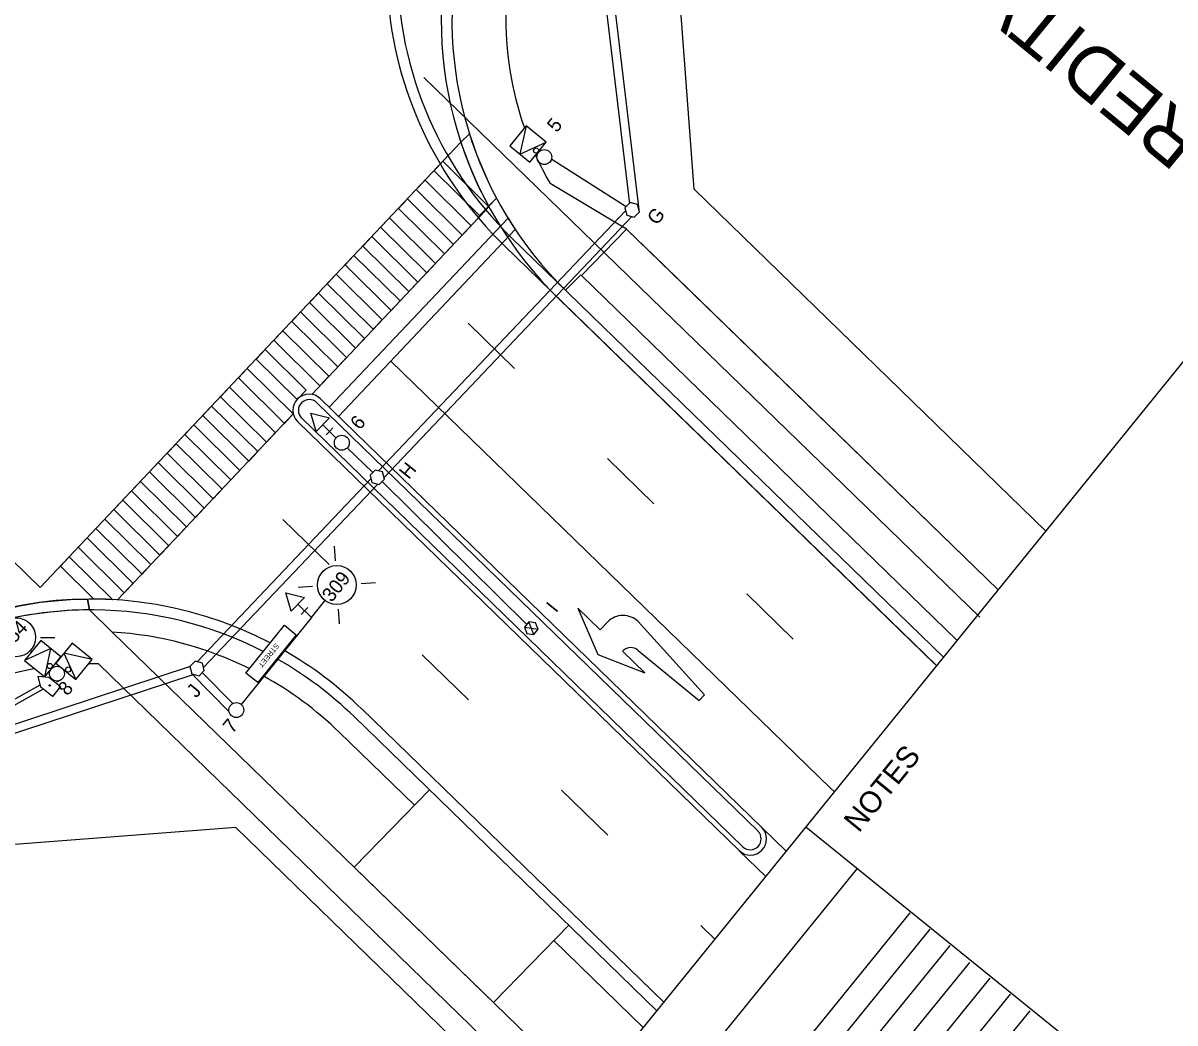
# Model space of a CAD drawing. Extents: x 592613 to 600223, y 4837996 to 4840103.
# Drawn here: x 593021.3 to 593074.7, y 4839279.7 to 4839326.1 of the extents above; entities that cross this region are included whole.
import ezdxf

# ---------------------------------------------------------------- set-up
doc = ezdxf.new("R2010")
doc.units = 0
for name, color, linetype in [('ENG_BORDER', 7, 'Continuous'), ('ENG_BUS-PAD', 7, 'Continuous'), ('ENG_CURB-BACK', 7, 'Continuous'), ('ENG_CURBSTOP', 7, 'Continuous'), ('ENG_EPAVT', 7, 'Continuous'), ('ENG_KILLSTRIP', 7, 'Continuous'), ('ENG_MULTI-TRAIL', 7, 'Continuous'), ('ENG_SH_MULTI-TRAIL', 7, 'Continuous'), ('ENG_SIDEWALK', 7, 'Continuous'), ('ENG_TITLEBLOCK', 7, 'Continuous'), ('ENG_TX_TITLEBLOCK', 7, 'Continuous'), ('Level 1', 7, 'Continuous'), ('Level 12', 7, 'Continuous'), ('Level 31', 7, 'Continuous'), ('Level 32', 7, 'Continuous'), ('Level 9', 7, 'Continuous'), ('PMK_LANE', 7, 'Continuous'), ('PMK_LANE_3-6', 7, 'Continuous'), ('ROW_ENG_ROW', 7, 'Continuous'), ('TCS_100mm-NEW', 7, 'Continuous'), ('TCS_50mm-NEW', 7, 'Continuous'), ('TCS_75mm-NEW', 7, 'Continuous'), ('TCS_ELEC-CHAMBER-NEW', 7, 'Continuous'), ('TCS_LUMINAIRE-NEW', 7, 'Continuous'), ('TCS_POLE-NEW', 7, 'Continuous'), ('TCS_PUSHBUTTON', 7, 'Continuous'), ('TCS_RADAR', 7, 'Continuous'), ('TCS_SIGN', 7, 'Continuous'), ('TCS_SIGNALHEAD', 7, 'Continuous')]:
    doc.layers.add(name, color=color, linetype=linetype)

msp = doc.modelspace()

# ---------------------------------------------------------------- linework, layer by layer
at = {"layer": 'ENG_BORDER'}
for p, q in [((593077.324, 4839272.823), (593057.566, 4839288.798)), ((593017.004, 4839234.009), (593059.952, 4839286.868))]:
    msp.add_line(p, q, dxfattribs=at)
at = {"layer": 'ENG_BUS-PAD'}
for p, q in [((593040.134, 4839290.531), (593036.65, 4839286.945)), ((593043.105, 4839280.674), (593036.65, 4839286.945)), ((593046.589, 4839284.26), (593043.105, 4839280.674))]:
    msp.add_line(p, q, dxfattribs=at)
at = {"layer": 'ENG_CURB-BACK'}
for p, q in [((593063.95, 4839296.672), (593043.953, 4839316.099)), ((593055.355, 4839288.609), (593034.912, 4839308.469)), ((593054.658, 4839287.891), (593034.204, 4839307.762)), ((593050.671, 4839280.294), (593036.643, 4839293.922))]:
    msp.add_line(p, q, dxfattribs=at)
for centre, radius, start, end in [((593058.676, 4839326.195), 17.5, 167.7306, 225.8289), ((593056.147, 4839328.651), 17.5, 178.3407, 225.8289), ((593034.558, 4839308.115), 0.5, 45.2459, 225.2459), ((593024.449, 4839281.37), 17.5, 62.8455, 116.2063), ((593024.449, 4839281.37), 17.5, 45.8289, 60.4988), ((593055.001, 4839288.255), 0.5, 226.4119, 45.2459)]:
    msp.add_arc(centre, radius, start, end, dxfattribs=at)
at = {"layer": 'ENG_CURBSTOP'}
for p, q in [((593041.985, 4839320.934), (593041.589, 4839320.535)), ((593043.243, 4839317.942), (593042.373, 4839317.064)), ((593024.375, 4839298.87), (593024.286, 4839299.369))]:
    msp.add_line(p, q, dxfattribs=at)
for points in [[(593043.243, 4839317.942), (593042.876, 4839317.571), (593042.412, 4839318.481), (593042.09, 4839319.2), (593041.59, 4839320.538), (593041.985, 4839320.934), (593042.33, 4839319.943), (593042.836, 4839318.755), (593043.006, 4839318.376)], [(593024.375, 4839298.87), (593023.359, 4839298.836), (593022.22, 4839298.728), (593021.245, 4839298.574), (593019.537, 4839298.161), (593019.155, 4839298.567), (593021.133, 4839299.062), (593021.663, 4839299.153), (593022.119, 4839299.219), (593022.783, 4839299.293), (593023.495, 4839299.345), (593024.042, 4839299.366), (593024.286, 4839299.369)]]:
    msp.add_lwpolyline(points, close=True, dxfattribs=at)
at = {"layer": 'ENG_EPAVT'}
for p, q in [((593063.634, 4839296.283), (593043.605, 4839315.74)), ((593055.529, 4839288.788), (593035.086, 4839308.648)), ((593054.484, 4839287.712), (593034.03, 4839307.583)), ((593050.988, 4839280.684), (593036.992, 4839294.281))]:
    msp.add_line(p, q, dxfattribs=at)
for centre, radius, start, end in [((593058.676, 4839326.195), 18, 166.783, 225.8289), ((593056.147, 4839328.651), 18, 184.2333, 225.8289), ((593034.558, 4839308.115), 0.75, 45.2459, 225.2459), ((593024.449, 4839281.37), 18, 62.5135, 142.6377), ((593024.449, 4839281.37), 16.5, 63.5712, 86.5779), ((593024.449, 4839281.37), 18, 45.8289, 60.2342), ((593024.449, 4839281.37), 16.5, 45.8289, 61.0962), ((593055.001, 4839288.255), 0.75, 226.4119, 45.2459)]:
    msp.add_arc(centre, radius, start, end, dxfattribs=at)
at = {"layer": 'ENG_KILLSTRIP'}
for p, q in [((593064.582, 4839297.452), (593047.178, 4839314.36)), ((593039.437, 4839289.814), (593035.946, 4839293.205)), ((593050.039, 4839279.514), (593045.892, 4839283.543))]:
    msp.add_line(p, q, dxfattribs=at)
at = {"layer": 'ENG_MULTI-TRAIL'}
for p, q in [((593049.269, 4839316.512), (593047.178, 4839314.36)), ((593066.479, 4839299.792), (593049.269, 4839316.512))]:
    msp.add_line(p, q, dxfattribs=at)
at = {"layer": 'ENG_SH_MULTI-TRAIL'}
for p, q in [((593039.879, 4839323.542), (593065.627, 4839298.528)), ((593046.133, 4839313.284), (593063.537, 4839296.376))]:
    msp.add_line(p, q, dxfattribs=at)
msp.add_lwpolyline([(593066.479, 4839299.792), (593050.537, 4839315.28), (593049.269, 4839316.512), (593047.178, 4839314.36), (593047.178, 4839314.36), (593064.582, 4839297.452)], dxfattribs=at)
at = {"layer": 'ENG_SIDEWALK'}
for p, q in [((593049.269, 4839316.512), (593045.728, 4839318.621)), ((593047.142, 4839314.395), (593046.419, 4839313.666)), ((593025.434, 4839297.841), (593024.375, 4839298.87)), ((593047.51, 4839276.395), (593025.434, 4839297.841)), ((593046.561, 4839275.225), (593024.799, 4839296.366))]:
    msp.add_line(p, q, dxfattribs=at)
for centre, start, end in [((593058.676, 4839326.195), 178.3521, 199.4407), ((593058.676, 4839326.195), 204.683, 210.3244), ((593024.449, 4839281.37), 88.6623, 90.4558), ((593024.449, 4839281.37), 100.1986, 113.33)]:
    msp.add_arc(centre, 15, start, end, dxfattribs=at)
at = {"layer": 'ENG_TITLEBLOCK'}
msp.add_line((593014.678, 4839235.899), (593087.391, 4839325.585), dxfattribs=at)
at = {"layer": 'Level 1'}
msp.add_line((593021.646, 4839296.981), (593021.705, 4839296.933), dxfattribs=at)
at = {"layer": 'Level 12'}
for p, q in [((593048.043, 4839297.948), (593047.013, 4839298.946)), ((593047.013, 4839298.946), (593047.934, 4839296.805)), ((593048.388, 4839298.304), (593048.043, 4839297.948)), ((593052.879, 4839294.931), (593049.802, 4839298.327)), ((593047.934, 4839296.805), (593050.104, 4839295.953)), ((593050.104, 4839295.953), (593049.073, 4839296.951)), ((593049.801, 4839296.983), (593052.624, 4839294.668)), ((593052.624, 4839294.668), (593052.879, 4839294.931))]:
    msp.add_line(p, q, dxfattribs=at)
for centre, radius, start, end in [((593049.107, 4839297.608), 1, 45.9051, 135.9273), ((593049.453, 4839296.624), 0.5, 45.8987, 135.9224)]:
    msp.add_arc(centre, radius, start, end, dxfattribs=at)
at = {"layer": 'Level 31'}
for p, q in [((593019.478, 4839231.999), (593062.405, 4839284.832)), ((593022.481, 4839233.799), (593063.333, 4839284.078)), ((593021.335, 4839230.491), (593064.261, 4839283.324)), ((593022.263, 4839229.736), (593065.161, 4839282.536)), ((593023.19, 4839228.983), (593066.104, 4839281.799)), ((593024.118, 4839228.229), (593067.045, 4839281.062)), ((593025.046, 4839227.475), (593067.959, 4839280.291))]:
    msp.add_line(p, q, dxfattribs=at)
at = {"layer": 'Level 9'}
msp.add_line((593023.084, 4839295.641), (593022.86, 4839295.522), dxfattribs=at)
at = {"layer": 'PMK_LANE'}
for p, q in [((593000.151, 4839321.221), (593022.099, 4839299.906)), ((593022.099, 4839299.906), (593041.589, 4839320.535)), ((593040.757, 4839319.655), (593040.345, 4839319.218)), ((593040.345, 4839319.218), (593042.478, 4839317.108)), ((593042.891, 4839317.544), (593040.757, 4839319.655)), ((593039.933, 4839318.782), (593039.521, 4839318.346)), ((593042.066, 4839316.672), (593039.933, 4839318.782)), ((593039.521, 4839318.346), (593041.654, 4839316.235)), ((593039.109, 4839317.91), (593038.697, 4839317.473)), ((593041.242, 4839315.799), (593039.109, 4839317.91)), ((593034.681, 4839308.855), (593042.891, 4839317.544)), ((593038.697, 4839317.473), (593040.83, 4839315.363)), ((593042.478, 4839317.108), (593042.891, 4839317.544)), ((593035.49, 4839308.255), (593043.773, 4839317.021)), ((593038.284, 4839317.037), (593037.872, 4839316.601)), ((593037.872, 4839316.601), (593040.005, 4839314.49)), ((593040.418, 4839314.927), (593038.284, 4839317.037)), ((593041.654, 4839316.235), (593042.066, 4839316.672)), ((593035.921, 4839307.837), (593044.106, 4839316.501)), ((593037.46, 4839316.165), (593037.048, 4839315.728)), ((593039.593, 4839314.054), (593037.46, 4839316.165)), ((593037.048, 4839315.728), (593039.181, 4839313.618)), ((593040.83, 4839315.363), (593041.242, 4839315.799)), ((593036.636, 4839315.292), (593036.224, 4839314.856)), ((593038.769, 4839313.182), (593036.636, 4839315.292)), ((593040.005, 4839314.49), (593040.418, 4839314.927)), ((593035.811, 4839314.42), (593035.399, 4839313.983)), ((593037.945, 4839312.309), (593035.811, 4839314.42)), ((593036.224, 4839314.856), (593038.357, 4839312.745)), ((593035.399, 4839313.983), (593037.532, 4839311.873)), ((593039.181, 4839313.618), (593039.593, 4839314.054)), ((593034.987, 4839313.547), (593034.575, 4839313.111)), ((593037.12, 4839311.437), (593034.987, 4839313.547)), ((593034.575, 4839313.111), (593036.708, 4839311)), ((593038.357, 4839312.745), (593038.769, 4839313.182)), ((593034.163, 4839312.675), (593033.751, 4839312.238)), ((593033.751, 4839312.238), (593035.884, 4839310.128)), ((593036.296, 4839310.564), (593034.163, 4839312.675)), ((593037.532, 4839311.873), (593037.945, 4839312.309)), ((593033.338, 4839311.802), (593032.926, 4839311.366)), ((593035.472, 4839309.692), (593033.338, 4839311.802)), ((593032.926, 4839311.366), (593035.059, 4839309.255)), ((593036.708, 4839311), (593037.12, 4839311.437)), ((593032.514, 4839310.93), (593032.102, 4839310.493)), ((593034.413, 4839309.051), (593032.514, 4839310.93)), ((593032.102, 4839310.493), (593034.001, 4839308.614)), ((593035.884, 4839310.128), (593036.296, 4839310.564)), ((593045.801, 4839303.151), (593038.34, 4839310.398)), ((593031.69, 4839310.057), (593031.278, 4839309.621)), ((593031.278, 4839309.621), (593033.411, 4839307.51)), ((593033.823, 4839307.947), (593031.69, 4839310.057)), ((593035.059, 4839309.255), (593035.472, 4839309.692)), ((593030.865, 4839309.185), (593030.453, 4839308.748)), ((593032.999, 4839307.074), (593030.865, 4839309.185)), ((593034.001, 4839308.614), (593034.413, 4839309.051)), ((593030.453, 4839308.748), (593032.587, 4839306.638)), ((593030.041, 4839308.312), (593029.629, 4839307.876)), ((593032.174, 4839306.202), (593030.041, 4839308.312)), ((593025.68, 4839299.328), (593033.826, 4839307.95)), ((593029.217, 4839307.44), (593028.805, 4839307.003)), ((593031.35, 4839305.329), (593029.217, 4839307.44)), ((593029.629, 4839307.876), (593031.762, 4839305.765)), ((593033.411, 4839307.51), (593033.823, 4839307.947)), ((593028.805, 4839307.003), (593030.938, 4839304.893)), ((593032.587, 4839306.638), (593032.999, 4839307.074)), ((593028.392, 4839306.567), (593027.98, 4839306.131)), ((593030.526, 4839304.457), (593028.392, 4839306.567)), ((593027.98, 4839306.131), (593030.114, 4839304.02)), ((593031.762, 4839305.765), (593032.174, 4839306.202)), ((593027.568, 4839305.695), (593027.156, 4839305.258)), ((593029.701, 4839303.584), (593027.568, 4839305.695)), ((593026.744, 4839304.822), (593026.332, 4839304.386)), ((593028.877, 4839302.712), (593026.744, 4839304.822)), ((593027.156, 4839305.258), (593029.289, 4839303.148)), ((593026.332, 4839304.386), (593028.465, 4839302.275)), ((593030.114, 4839304.02), (593030.526, 4839304.457)), ((593025.92, 4839303.95), (593025.507, 4839303.513)), ((593028.053, 4839301.839), (593025.92, 4839303.95)), ((593025.507, 4839303.513), (593027.641, 4839301.403)), ((593029.289, 4839303.148), (593029.701, 4839303.584)), ((593025.095, 4839303.077), (593024.683, 4839302.641)), ((593024.683, 4839302.641), (593026.816, 4839300.53)), ((593027.228, 4839300.967), (593025.095, 4839303.077)), ((593028.465, 4839302.275), (593028.877, 4839302.712)), ((593052.257, 4839296.879), (593045.801, 4839303.151)), ((593024.271, 4839302.205), (593023.859, 4839301.768)), ((593026.404, 4839300.094), (593024.271, 4839302.205)), ((593023.859, 4839301.768), (593025.992, 4839299.658)), ((593027.641, 4839301.403), (593028.053, 4839301.839)), ((593023.447, 4839301.332), (593023.034, 4839300.896)), ((593025.458, 4839299.342), (593023.447, 4839301.332)), ((593023.034, 4839300.896), (593024.577, 4839299.37)), ((593026.816, 4839300.53), (593027.228, 4839300.967)), ((593025.992, 4839299.658), (593026.404, 4839300.094)), ((593058.713, 4839290.607), (593052.257, 4839296.879)), ((593058.891, 4839290.433), (593058.713, 4839290.607)), ((593055.553, 4839288.763), (593056.664, 4839287.686)), ((593054.488, 4839287.709), (593055.716, 4839286.517))]:
    msp.add_line(p, q, dxfattribs=at)
msp.add_lwpolyline([(593043.773, 4839317.021), (593044.106, 4839316.501), (593035.921, 4839307.837), (593035.49, 4839308.255)], close=True, dxfattribs=at)
msp.add_lwpolyline([(593030.938, 4839304.893), (593031.183, 4839305.152), (593031.35, 4839305.329)], dxfattribs=at)
msp.add_arc((593024.449, 4839281.37), 18, 86.7865, 89.5933, dxfattribs=at)
at = {"layer": 'PMK_LANE_3-6'}
for p, q in [((593044.072, 4839310.058), (593041.92, 4839312.149)), ((593050.528, 4839303.786), (593048.376, 4839305.877)), ((593033.335, 4839303.062), (593035.487, 4839300.971)), ((593056.984, 4839297.514), (593054.832, 4839299.605)), ((593039.791, 4839296.79), (593041.943, 4839294.699)), ((593046.247, 4839290.518), (593048.399, 4839288.427)), ((593052.703, 4839284.246), (593053.359, 4839283.609))]:
    msp.add_line(p, q, dxfattribs=at)
at = {"layer": 'ROW_ENG_ROW'}
for p, q in [((593052.389, 4839318.36), (593050.733, 4839340.727)), ((593068.692, 4839302.522), (593052.389, 4839318.36)), ((593031.168, 4839288.785), (593010.654, 4839287.203)), ((593045.929, 4839274.445), (593031.168, 4839288.785))]:
    msp.add_line(p, q, dxfattribs=at)
at = {"layer": 'TCS_100mm-NEW'}
for p, q in [((593049.863, 4839317.287), (593047.783, 4839334.814)), ((593038.032, 4839305.002), (593049.512, 4839317.094)), ((593036.32, 4839306.371), (593037.503, 4839305.228)), ((593029.667, 4839296.192), (593037.74, 4839304.696)), ((593017.452, 4839292.021), (593029.189, 4839295.876)), ((593029.609, 4839295.973), (593031.025, 4839294.534)), ((593022.229, 4839295.188), (593017.538, 4839292.568))]:
    msp.add_line(p, q, dxfattribs=at)
at = {"layer": 'TCS_50mm-NEW'}
for p, q in [((593049.413, 4839317.684), (593047.4, 4839334.652)), ((593037.769, 4839305.307), (593049.202, 4839317.349)), ((593029.372, 4839296.463), (593037.423, 4839304.942)), ((593044.637, 4839298.198), (593037.937, 4839304.816)), ((593017.538, 4839292.471), (593029.064, 4839296.256)), ((593029.106, 4839295.914), (593030.849, 4839294.142)), ((593017.204, 4839292.658), (593022.1, 4839295.402))]:
    msp.add_line(p, q, dxfattribs=at)
at = {"layer": 'TCS_75mm-NEW'}
msp.add_line((593045.809, 4839319.756), (593049.241, 4839317.557), dxfattribs=at)
at = {"layer": 'TCS_ELEC-CHAMBER-NEW'}
for p, q in [((593049.436, 4839317.741), (593049.192, 4839317.496)), ((593049.77, 4839317.651), (593049.436, 4839317.741)), ((593049.859, 4839317.318), (593049.77, 4839317.651)), ((593049.192, 4839317.496), (593049.281, 4839317.163)), ((593049.281, 4839317.163), (593049.615, 4839317.073)), ((593049.615, 4839317.073), (593049.859, 4839317.318)), ((593037.625, 4839305.35), (593037.381, 4839305.106)), ((593037.959, 4839305.261), (593037.625, 4839305.35)), ((593037.381, 4839305.106), (593037.47, 4839304.772)), ((593037.47, 4839304.772), (593037.804, 4839304.683)), ((593037.804, 4839304.683), (593038.049, 4839304.927)), ((593038.049, 4839304.927), (593037.959, 4839305.261)), ((593044.737, 4839298.322), (593044.537, 4839298.074)), ((593044.537, 4839298.074), (593045.167, 4839297.975)), ((593044.537, 4839298.074), (593044.651, 4839297.777)), ((593044.966, 4839297.727), (593044.737, 4839298.322)), ((593045.052, 4839298.273), (593044.737, 4839298.322)), ((593044.966, 4839297.727), (593045.167, 4839297.975)), ((593045.167, 4839297.975), (593045.052, 4839298.273)), ((593044.651, 4839297.777), (593044.966, 4839297.727)), ((593029.278, 4839296.488), (593029.034, 4839296.243)), ((593029.034, 4839296.243), (593029.123, 4839295.91)), ((593029.612, 4839296.398), (593029.278, 4839296.488)), ((593029.701, 4839296.065), (593029.612, 4839296.398)), ((593029.123, 4839295.91), (593029.457, 4839295.82)), ((593029.457, 4839295.82), (593029.701, 4839296.065))]:
    msp.add_line(p, q, dxfattribs=at)
at = {"layer": 'TCS_LUMINAIRE-NEW'}
for p, q in [((593035.773, 4839301.144), (593035.732, 4839301.818)), ((593036.963, 4839300.089), (593037.638, 4839300.13)), ((593034.718, 4839299.954), (593034.044, 4839299.913)), ((593034.663, 4839298.51), (593035.293, 4839299.287)), ((593035.908, 4839298.899), (593035.949, 4839298.225)), ((593034.663, 4839298.511), (593031.411, 4839294.486)), ((593022.108, 4839297.589), (593022.784, 4839297.582))]:
    msp.add_line(p, q, dxfattribs=at)
for centre in [(593035.841, 4839300.021), (593020.984, 4839297.6)]:
    msp.add_circle(centre, 0.9, dxfattribs=at)
at = {"layer": 'TCS_POLE-NEW'}
for centre in [(593045.454, 4839319.849), (593036.072, 4839306.612), (593022.872, 4839295.913), (593031.183, 4839294.226)]:
    msp.add_circle(centre, 0.346, dxfattribs=at)
at = {"layer": 'TCS_PUSHBUTTON'}
for centre in [(593045.073, 4839320.155), (593022.544, 4839296.269), (593023.389, 4839296.106)]:
    msp.add_circle(centre, 0.12, dxfattribs=at)
at = {"layer": 'TCS_RADAR'}
msp.add_lwpolyline([(593023.045, 4839295.314), (593022.671, 4839294.853), (593022.128, 4839295.294), (593021.998, 4839295.793), (593022.503, 4839295.754)], close=True, dxfattribs=at)
msp.add_circle((593022.538, 4839295.37), 0.0323, dxfattribs=at)
at = {"layer": 'TCS_SIGN'}
msp.add_lwpolyline([(593033.964, 4839297.712), (593032.176, 4839295.499), (593031.629, 4839295.942), (593033.417, 4839298.155)], close=True, dxfattribs=at)
at = {"layer": 'TCS_SIGNALHEAD'}
for p, q in [((593044.61, 4839321.3), (593043.856, 4839320.367)), ((593043.856, 4839320.367), (593044.789, 4839319.612)), ((593044.789, 4839319.612), (593045.543, 4839320.546)), ((593034.639, 4839307.984), (593035.494, 4839307.765)), ((593034.878, 4839307.135), (593034.639, 4839307.984)), ((593035.494, 4839307.765), (593034.878, 4839307.135)), ((593035.186, 4839307.45), (593035.818, 4839306.833)), ((593035.502, 4839307.141), (593035.348, 4839306.984)), ((593035.502, 4839307.141), (593035.656, 4839307.299)), ((593033.482, 4839299.662), (593034.338, 4839299.443)), ((593033.722, 4839298.812), (593033.482, 4839299.662)), ((593034.338, 4839299.443), (593033.722, 4839298.812)), ((593034.029, 4839299.128), (593034.662, 4839298.511)), ((593034.345, 4839298.819), (593034.5, 4839298.977)), ((593034.345, 4839298.819), (593034.191, 4839298.661)), ((593022.126, 4839297.453), (593021.372, 4839296.52)), ((593023.06, 4839296.699), (593022.126, 4839297.453)), ((593023.576, 4839297.33), (593022.818, 4839296.4)), ((593024.507, 4839296.572), (593023.576, 4839297.33)), ((593022.306, 4839295.765), (593023.06, 4839296.699)), ((593022.818, 4839296.4), (593023.749, 4839295.642))]:
    msp.add_line(p, q, dxfattribs=at)
for points in [[(593045.543, 4839320.546), (593044.61, 4839321.3), (593044.322, 4839319.99), (593044.322, 4839319.99)], [(593035.494, 4839307.765), (593034.878, 4839307.135), (593034.639, 4839307.984), (593034.639, 4839307.984)], [(593034.338, 4839299.443), (593033.722, 4839298.812), (593033.482, 4839299.662), (593033.482, 4839299.662)], [(593021.372, 4839296.52), (593022.306, 4839295.765), (593022.593, 4839297.076), (593022.593, 4839297.076)], [(593023.749, 4839295.642), (593024.507, 4839296.572), (593023.197, 4839296.865), (593023.197, 4839296.865)]]:
    msp.add_lwpolyline(points, close=True, dxfattribs=at)

# ---------------------------------------------------------------- texts
at = {"layer": 'ENG_TX_TITLEBLOCK'}
msp.add_text('NOTES', height=1, rotation=50.9062, dxfattribs=at).set_placement((593060.027, 4839288.502))
at = {"layer": 'Level 32'}
msp.add_text('CREDITVIEW ROAD', height=2.5, rotation=140.5921, dxfattribs=at).set_placement((593078.063, 4839319.521))
at = {"layer": 'TCS_ELEC-CHAMBER-NEW'}
for s, p in [('G', (593050.664, 4839316.655)), ('H', (593039.175, 4839304.88)), ('I', (593045.995, 4839298.702)), ('J', (593029.334, 4839294.755))]:
    msp.add_text(s, height=0.65, rotation=51.0574, dxfattribs=at).set_placement(p)
at = {"layer": 'TCS_LUMINAIRE-NEW'}
for s, rotation, p in [('309', 51.283, (593035.602, 4839299.188)), ('154', 47.2608, (593020.584, 4839296.939))]:
    msp.add_text(s, height=0.65, rotation=rotation, dxfattribs=at).set_placement(p)
at = {"layer": 'TCS_POLE-NEW'}
for s, p in [('5', (593046.027, 4839320.951)), ('6', (593036.911, 4839307.168)), ('8', (593023.366, 4839294.851)), ('7', (593031.007, 4839293.106))]:
    msp.add_text(s, height=0.65, rotation=51.0574, dxfattribs=at).set_placement(p)
at = {"layer": 'TCS_SIGN'}
msp.add_text('STREET', height=0.2407, rotation=231.0574, dxfattribs=at).set_placement((593033.006, 4839297.343))

doc.saveas('drawing.dxf')
